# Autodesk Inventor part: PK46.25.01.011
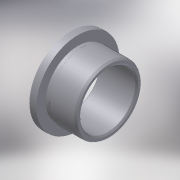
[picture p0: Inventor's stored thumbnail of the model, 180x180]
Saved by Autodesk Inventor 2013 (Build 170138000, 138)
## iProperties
Created: 2005-04
Part Number: PK46.25.01.011
Material: Steel, Mild
Document SubType Name: Modeling
Designer: salex
Manufacturer: Standard
Standards Organization: Custom
Density: 7.86 g/cm^3
Author: salex
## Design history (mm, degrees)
sketch "Эскиз1"
  geometry: L1 (0, 0)-(56.407, 0); L2 (0, 40)-(0, 60); L3 (0, 60)-(10, 60); L4 (10, 60)-(10, 46.5); L5 (10, 46.5)-(15, 46.5); L6 (15, 46.5)-(16, 47.5); L7 (16, 47.5)-(55, 47.5); L8 (55, 47.5)-(55, 40); L9 (55, 40)-(0, 40)
  constraints: 18 end point, 5 parallel, 2 perpendicular, 1 horizontal, 1 other
  dimensions: "d0" = 0 distance from line of L1.start L2; "d1" = 10 distance of L2.end L3.end; "d2" = 5 distance of L4.end L5.end; "d3" = 45 deg angle of L6 L5; "d4" = 55 distance between parallel lines of L8 L2; "d5" = 80 diameter of L9 L1; "d6" = 120 diameter of L3 L1; "d7" = 95 diameter of L7 L1; "d8" = 93 diameter of L5 L1
revolve "Вращение1" sketch "Эскиз1" stored, may be unused: angle "d9" = 90 deg
chamfer "Фаска1" distance "d10" = 2; stored, may be unused: second distance "d11" = 2, angle "d12" = 45 deg
chamfer "Фаска2" distance "d13" = 3; stored, may be unused: second distance "d14" = 2, angle "d15" = 30 deg
body "Solid1"
